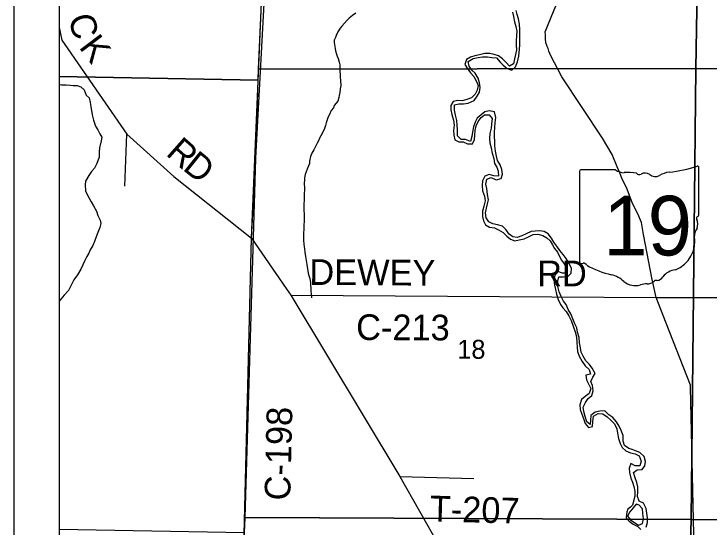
# Model space of a CAD drawing. Extents: x 0 to 34, y 0 to 22.
# Drawn here: x 2 to 3.538, y 17.445 to 18.58 of the extents above; entities that cross this region are included whole.
import ezdxf

# ---------------------------------------------------------------- set-up
doc = ezdxf.new("R2010")
doc.units = 0
for name, color, linetype in [('Default', 7, 'Continuous'), ('GM_X_County_Road', 7, 'Continuous'), ('GM_X_County_Road_Text', 7, 'Continuous'), ('GM_X_Minor_River', 7, 'Continuous'), ('GM_X_Section', 7, 'Continuous'), ('GM_X_Section_Text', 7, 'Continuous'), ('GM_X_State_Location', 7, 'Continuous'), ('GM_X_State_Route', 7, 'Continuous'), ('GM_X_State_Shield', 7, 'Continuous'), ('GM_X_Township', 7, 'Continuous'), ('GM_X_Township_Road', 7, 'Continuous'), ('GM_X_Township_Road_Text', 7, 'Continuous'), ('SH_Cut_Line', 7, 'Continuous'), ('SH_Data', 7, 'Continuous')]:
    doc.layers.add(name, color=color, linetype=linetype)

msp = doc.modelspace()

# ---------------------------------------------------------------- linework, layer by layer
at = {"layer": 'Default'}
for points in [[(2.1, 19.4698), (2.1, 18.4416), (2.54, 18.4332), (2.5413, 18.4578), (2.5849, 19.435)], [(2.1, 18.4416), (2.1, 17.4406), (2.5103, 17.4328), (2.5117, 17.4662), (2.54, 18.4332)]]:
    msp.add_lwpolyline(points, close=True, dxfattribs=at)
at = {"layer": 'GM_X_County_Road'}
for p, q in [((2.5258, 18.084), (2.5713, 18.9402)), ((2.5095, 17.4283), (2.5258, 18.084)), ((2.6125, 17.9578), (3.4203, 17.953))]:
    msp.add_line(p, q, dxfattribs=at)
for points in [[(2.1, 18.5494), (2.1061, 18.5215), (2.2501, 18.3137), (2.3537, 18.2205), (2.5258, 18.084)], [(2.5258, 18.084), (2.6022, 17.9726), (2.6125, 17.9578)], [(2.6125, 17.9578), (2.8536, 17.5572), (2.9844, 17.3269), (3.0036, 17.2741), (3.0215, 17.2032), (3.0902, 16.9681)], [(3.4203, 17.953), (3.775, 17.9527), (4.5096, 17.9519)]]:
    msp.add_lwpolyline(points, dxfattribs=at)
at = {"layer": 'GM_X_Minor_River'}
for points in [[(2.7565, 18.5813), (2.7488, 18.5761), (2.7415, 18.5701), (2.7369, 18.5656), (2.7254, 18.5528), (2.7219, 18.5479), (2.7162, 18.54), (2.7127, 18.5321), (2.7111, 18.5275), (2.7087, 18.5219), (2.7087, 18.5165), (2.7097, 18.5074), (2.7104, 18.5029), (2.7115, 18.4983), (2.7133, 18.4911), (2.7152, 18.4861), (2.717, 18.4808), (2.7196, 18.4728), (2.7206, 18.4675), (2.7209, 18.4595), (2.7208, 18.4526), (2.7215, 18.4458), (2.7218, 18.4401), (2.7225, 18.4325), (2.7231, 18.4215), (2.7219, 18.4143), (2.7211, 18.406), (2.7191, 18.3995), (2.7187, 18.395), (2.7163, 18.387), (2.7086, 18.3769), (2.7067, 18.3723), (2.702, 18.3659), (2.6978, 18.3576), (2.6954, 18.352), (2.6931, 18.3452), (2.6907, 18.3391), (2.6891, 18.333), (2.6868, 18.3262), (2.6833, 18.3183)], [(3.0478, 18.1805), (3.0462, 18.1938), (3.0438, 18.2033), (3.0464, 18.2147), (3.056, 18.2178), (3.0665, 18.2126), (3.0775, 18.2157), (3.0805, 18.2251), (3.0792, 18.2358), (3.0757, 18.2458), (3.0695, 18.2554), (3.0675, 18.2653), (3.0655, 18.276), (3.0639, 18.2878), (3.0634, 18.2973), (3.063, 18.3087), (3.0629, 18.3182), (3.0635, 18.3289), (3.0642, 18.3387), (3.0657, 18.3508), (3.063, 18.3634), (3.0513, 18.3656), (3.0413, 18.3629), (3.0332, 18.3566), (3.025, 18.3493), (3.0206, 18.3407), (3.0166, 18.3298), (3.014, 18.3184), (3.0129, 18.3086), (3.0096, 18.2977), (2.9991, 18.3021), (2.9893, 18.302), (2.9811, 18.3102), (2.9811, 18.3239), (2.9802, 18.3334), (2.9798, 18.3444), (2.9771, 18.3555), (2.9747, 18.3666), (2.9743, 18.3784), (2.9842, 18.3808), (2.9944, 18.3809), (3.0051, 18.3821), (3.0181, 18.3882), (3.0248, 18.3979), (3.03, 18.4068), (3.0314, 18.4171), (3.0302, 18.4273), (3.0267, 18.4373), (3.0205, 18.4485), (3.0127, 18.4552), (3.0073, 18.464), (3.0046, 18.4747), (3.0157, 18.4809), (3.0268, 18.4836), (3.0363, 18.4845), (3.0473, 18.485), (3.0571, 18.4832), (3.0677, 18.4829), (3.0758, 18.4732), (3.0824, 18.4662), (3.091, 18.4587), (3.1015, 18.455), (3.1093, 18.4624), (3.1141, 18.474), (3.1167, 18.4865), (3.1183, 18.5016), (3.1193, 18.5111), (3.1189, 18.5229), (3.1188, 18.5339), (3.1187, 18.5445), (3.1186, 18.5567), (3.1159, 18.5689), (3.1135, 18.5784), (3.1111, 18.5876)], [(3.1027, 18.5833), (3.1054, 18.5737), (3.1074, 18.5623), (3.1105, 18.5519), (3.1125, 18.5416), (3.1115, 18.5318), (3.1112, 18.5204), (3.1109, 18.5102), (3.1114, 18.5003), (3.1092, 18.4901), (3.1071, 18.4807), (3.1049, 18.4693), (3.096, 18.4639), (3.0887, 18.4721), (3.0809, 18.4806), (3.072, 18.4873), (3.0626, 18.4902), (3.0528, 18.492), (3.0418, 18.4919), (3.03, 18.4892), (3.0193, 18.4869), (3.0101, 18.4841)], [(3.0101, 18.4841), (3.0009, 18.479), (2.9972, 18.4681), (3.0022, 18.4596), (3.0096, 18.4496), (3.0173, 18.441), (3.0235, 18.4306), (3.0266, 18.4214), (3.0244, 18.4112), (3.02, 18.4026), (3.0119, 18.3944), (3.0015, 18.3902), (2.9916, 18.3874), (2.9817, 18.3884), (2.9718, 18.3864), (2.9666, 18.3771), (2.9668, 18.3676), (2.9688, 18.3573), (2.9726, 18.3446), (2.9738, 18.3336), (2.9727, 18.3219), (2.9728, 18.312), (2.9756, 18.3013), (2.9842, 18.2969), (2.994, 18.2966), (3.003, 18.2922), (3.014, 18.2926), (3.0188, 18.3024), (3.0195, 18.3118), (3.0201, 18.3221), (3.0223, 18.3323), (3.0271, 18.3416), (3.0334, 18.3509), (3.0412, 18.3568), (3.0514, 18.3565), (3.0576, 18.3488), (3.0565, 18.3363), (3.0555, 18.3268), (3.0529, 18.3151), (3.0523, 18.3045), (3.0528, 18.2946), (3.0555, 18.2835), (3.0578, 18.2717), (3.0613, 18.2602), (3.0633, 18.2491), (3.0684, 18.241), (3.0712, 18.2318), (3.0716, 18.2208), (3.0614, 18.2215), (3.0509, 18.2248), (3.042, 18.2209), (3.0365, 18.2108), (3.0358, 18.2002), (3.0366, 18.1887), (3.0408, 18.1769), (3.0425, 18.1662), (3.0395, 18.1549), (3.0365, 18.1436), (3.0362, 18.1318), (3.0386, 18.1219), (3.0433, 18.1134), (3.0519, 18.1082), (3.0628, 18.1068), (3.0722, 18.102), (3.0819, 18.0968), (3.09, 18.0886), (3.0982, 18.0819), (3.1079, 18.0778), (3.1179, 18.0802), (3.1285, 18.0822), (3.1385, 18.0868), (3.1485, 18.0919), (3.1588, 18.0931), (3.1697, 18.0898), (3.179, 18.0846), (3.1861, 18.0779), (3.1915, 18.0694), (3.1958, 18.061), (3.2021, 18.0532), (3.2067, 18.0436), (3.2114, 18.0351), (3.2173, 18.0274), (3.2227, 18.0177), (3.2239, 18.0067), (3.2133, 18.0062), (3.2032, 18.0099), (3.1961, 18.0021), (3.194, 17.9919), (3.1955, 17.9797), (3.1983, 17.9705), (3.2003, 17.9599), (3.2038, 17.9484), (3.2092, 17.9376), (3.2143, 17.9295), (3.2213, 17.9221), (3.2278, 17.9124), (3.2329, 17.902), (3.2381, 17.8874), (3.2413, 17.8767), (3.2444, 17.8656), (3.2452, 17.8531)], [(2.1, 18.4239), (2.1056, 18.4232), (2.1159, 18.4227), (2.1242, 18.4222), (2.1314, 18.4218), (2.1397, 18.4213), (2.1484, 18.4186), (2.1556, 18.412), (2.1596, 18.4002), (2.1667, 18.3944), (2.1689, 18.3842), (2.1703, 18.3751), (2.1728, 18.3564), (2.1757, 18.345), (2.1808, 18.3313), (2.1853, 18.3233), (2.1901, 18.3149), (2.1942, 18.3072), (2.193, 18.2989), (2.1894, 18.2838), (2.1889, 18.2743), (2.1884, 18.2629), (2.1837, 18.2489), (2.1779, 18.2387), (2.1717, 18.2316), (2.1655, 18.2221), (2.1586, 18.2101), (2.1573, 18.2021), (2.1587, 18.1884), (2.1631, 18.1793), (2.1709, 18.1644), (2.1761, 18.1552), (2.1825, 18.1438), (2.1858, 18.1342), (2.1906, 18.1239), (2.192, 18.1167), (2.19, 18.1073), (2.1857, 18.0963), (2.1822, 18.0868), (2.1779, 18.0766), (2.1748, 18.0679), (2.169, 18.0581), (2.1658, 18.0506), (2.1616, 18.043), (2.1569, 18.0347), (2.1484, 18.0155), (2.1403, 18.003), (2.1326, 17.9917), (2.1252, 17.977), (2.1209, 17.9683), (2.1109, 17.9578), (2.104, 17.9488), (2.1, 17.9444)], [(2.6833, 18.3183), (2.679, 18.3104), (2.6763, 18.3051), (2.6736, 18.2994), (2.6709, 18.2938), (2.6658, 18.284), (2.6631, 18.2791), (2.6588, 18.2715), (2.6557, 18.2647), (2.6541, 18.2545), (2.6537, 18.2492), (2.6517, 18.2439), (2.649, 18.2367), (2.6443, 18.225), (2.6431, 18.2174), (2.6426, 18.2128), (2.6421, 18.2049), (2.6424, 18.1946), (2.6424, 18.1901), (2.6419, 18.1825), (2.6415, 18.1442), (2.6418, 18.1385), (2.6421, 18.1316), (2.642, 18.1218), (2.6415, 18.1123), (2.6413, 18.1017), (2.6409, 18.0971), (2.6404, 18.0884), (2.6403, 18.0793), (2.641, 18.0705), (2.6417, 18.0648), (2.6424, 18.0603), (2.6434, 18.0527), (2.6449, 18.0435), (2.6474, 18.0302), (2.6481, 18.0257), (2.6491, 18.0162), (2.6498, 18.0116), (2.6509, 18.0067), (2.652, 18.0013), (2.6545, 17.9949), (2.6559, 17.9853), (2.6563, 17.9808), (2.6569, 17.9728), (2.6569, 17.9683), (2.6576, 17.9595), (2.6586, 17.9519)], [(3.1134, 18.0853), (3.1036, 18.0867), (3.0958, 18.093), (3.0878, 18.1034), (3.0808, 18.1105), (3.0695, 18.1134), (3.0597, 18.1156), (3.0507, 18.12), (3.0449, 18.1289), (3.0432, 18.1396), (3.0454, 18.1505), (3.0472, 18.16), (3.0501, 18.169), (3.0478, 18.1805)], [(3.3987, 17.4449), (3.4016, 17.4554), (3.4012, 17.4657), (3.4003, 17.4756), (3.3987, 17.4863), (3.3926, 17.4982), (3.3832, 17.5023), (3.3793, 17.513), (3.3803, 17.5236), (3.3799, 17.5342), (3.3779, 17.5438), (3.3743, 17.5541), (3.3705, 17.5656), (3.3786, 17.5715), (3.3893, 17.5727), (3.3955, 17.5805), (3.3969, 17.5904), (3.3938, 17.6011), (3.3846, 17.6101), (3.3751, 17.6137), (3.3677, 17.6164), (3.3602, 17.6191), (3.3509, 17.6254), (3.3477, 17.635), (3.3477, 17.6475), (3.3431, 17.659), (3.3384, 17.6683), (3.3326, 17.6776), (3.3245, 17.6876), (3.3156, 17.6936), (3.3071, 17.7018), (3.2957, 17.7013), (3.2854, 17.6993), (3.2764, 17.6916), (3.275, 17.6814), (3.2744, 17.6716), (3.267, 17.6778), (3.2635, 17.6893), (3.2604, 17.7004), (3.2595, 17.7099), (3.264, 17.7208), (3.2699, 17.7294), (3.278, 17.7364), (3.281, 17.7466), (3.2798, 17.758), (3.2758, 17.7672), (3.2803, 17.7769), (3.2858, 17.7848), (3.2793, 17.7963), (3.2734, 17.8045), (3.2653, 17.813), (3.2588, 17.8227), (3.2545, 17.8316), (3.2532, 17.8411), (3.2508, 17.8522), (3.25, 17.864), (3.2469, 17.8762), (3.2449, 17.8857), (3.241, 17.8946), (3.2364, 17.9053), (3.2321, 17.9165), (3.2263, 17.9265), (3.2213, 17.9369), (3.2158, 17.9446), (3.2104, 17.955), (3.2061, 17.9654), (3.203, 17.9773), (3.203, 17.9886), (3.2055, 17.9981), (3.2154, 17.9986), (3.2249, 17.9991), (3.2323, 18.0068), (3.2333, 18.0167), (3.2279, 18.0282), (3.2214, 18.0386), (3.2148, 18.0479), (3.2078, 18.0565), (3.2009, 18.0662), (3.1943, 18.0751), (3.1889, 18.0839), (3.1815, 18.0933), (3.1726, 18.0988), (3.1628, 18.0999), (3.1533, 18.0994), (3.1438, 18.0989), (3.133, 18.0935), (3.1234, 18.0892), (3.1134, 18.0853)], [(3.2452, 17.8531), (3.246, 17.8428), (3.2469, 17.8333), (3.2501, 17.823), (3.2566, 17.811), (3.2635, 17.8013), (3.2724, 17.7935), (3.2751, 17.7832), (3.2648, 17.7808), (3.2668, 17.7709), (3.2711, 17.7616), (3.2762, 17.7516), (3.2725, 17.7403), (3.2636, 17.7337), (3.2558, 17.7271), (3.2521, 17.7155), (3.2525, 17.7048), (3.2564, 17.6944), (3.26, 17.6849), (3.2635, 17.6738), (3.2708, 17.6652), (3.28, 17.6676), (3.2806, 17.6786), (3.2821, 17.6903), (3.2921, 17.6961), (3.3023, 17.6955), (3.3124, 17.6887), (3.3205, 17.6817), (3.3283, 17.6731), (3.3333, 17.662), (3.3353, 17.6524), (3.3376, 17.641), (3.3408, 17.6299), (3.3451, 17.621), (3.3536, 17.6136), (3.3641, 17.6091), (3.3739, 17.6073), (3.3829, 17.6025), (3.3875, 17.591), (3.3845, 17.5804), (3.3739, 17.5807), (3.3646, 17.5855), (3.3609, 17.575), (3.3614, 17.5655), (3.3645, 17.5529), (3.3684, 17.5441), (3.3715, 17.5345), (3.3735, 17.5246), (3.3736, 17.5135), (3.3682, 17.4936), (3.3639, 17.4895), (3.3577, 17.4847), (3.356, 17.4791), (3.3541, 17.4659), (3.3611, 17.4581), (3.3697, 17.4518), (3.3798, 17.4465), (3.3868, 17.4399)], [(3.3762, 17.4956), (3.3695, 17.4878), (3.3621, 17.4789), (3.3573, 17.4696), (3.3639, 17.4614), (3.3732, 17.4543), (3.3814, 17.4495), (3.3906, 17.4531), (3.3928, 17.4637)], [(3.3928, 17.4637), (3.3912, 17.4751), (3.3903, 17.4854), (3.3833, 17.4932), (3.3762, 17.4956)]]:
    msp.add_lwpolyline(points, dxfattribs=at)
at = {"layer": 'GM_X_Section'}
for points in [[(3.5253, 19.4614), (3.5082, 18.4594), (2.5413, 18.4578), (2.5849, 19.435), (2.5858, 19.465)], [(4.5252, 19.4639), (4.517, 18.4555), (3.5082, 18.4594), (3.5253, 19.4614)], [(3.5082, 18.4594), (3.4982, 17.462), (2.5117, 17.4662), (2.54, 18.4332), (2.5413, 18.4578)], [(4.517, 18.4555), (4.4991, 17.4554), (3.4982, 17.462), (3.5082, 18.4594)], [(3.4982, 17.462), (3.4692, 16.4646), (2.4877, 16.4726), (2.5103, 17.4328), (2.5117, 17.4662)], [(4.4991, 17.4554), (4.4826, 16.453), (3.4692, 16.4646), (3.4982, 17.462)]]:
    msp.add_lwpolyline(points, close=True, dxfattribs=at)
at = {"layer": 'GM_X_State_Route'}
msp.add_lwpolyline([(3.5068, 17.2998), (3.4971, 17.7208), (3.4968, 17.7546), (3.4965, 17.7592), (3.4424, 17.8956), (3.4203, 17.953), (3.4116, 17.9928), (3.3929, 18.0918), (3.388, 18.1189), (3.3803, 18.1376), (3.3689, 18.159), (3.3659, 18.1663), (3.3612, 18.1808), (3.355, 18.1957), (3.3454, 18.2144), (3.3399, 18.2282), (3.3341, 18.2415), (3.3231, 18.2687), (3.302, 18.305), (3.2122, 18.4404), (3.1956, 18.4717), (3.1879, 18.487), (3.1835, 18.4977), (3.1816, 18.5031), (3.1798, 18.5077), (3.1773, 18.5142), (3.1769, 18.5161), (3.1755, 18.5256), (3.1756, 18.529), (3.1757, 18.5343), (3.1754, 18.5404), (3.2116, 18.6305)], dxfattribs=at)
at = {"layer": 'GM_X_State_Shield'}
for p, q in [((3.5149, 18.1354), (3.5149, 18.2401)), ((3.2512, 18.2317), (3.2512, 18.0315)), ((3.331, 18.2351), (3.2538, 18.2351)), ((3.5149, 18.1354), (3.5149, 18.1354))]:
    msp.add_line(p, q, dxfattribs=at)
for centre, radius, start, end in [((3.421, 18.5079), 0.2796, 275.8445, 288.9065), ((3.512, 18.2405), 0.00294, 351.8621, 97.738), ((3.2542, 18.2321), 0.00305, 98.1301, 188.1301), ((3.3494, 18.2583), 0.0296, 231.6195, 271.1119), ((3.3592, 18.1228), 0.1064, 80.4867, 94.9883), ((3.3834, 18.2331), 0.00855, 219.7921, 297.1024), ((3.3959, 18.21), 0.0178, 54.4667, 119.1411), ((3.4189, 18.2417), 0.0214, 233.8562, 294.8282), ((3.4566, 18.174), 0.0563, 97.3462, 120.7689), ((3.5142, 18.1277), 0.00454, 107.944, 210.337), ((3.5118, 18.135), 0.00314, 289.6038, 7.7341), ((3.4853, 18.1145), 0.0273, 340.033, 23.6496), ((3.5254, 18.0916), 0.0198, 136.8065, 186.9296), ((3.4366, 18.0783), 0.0699, 292.3089, 8.9858), ((3.2543, 18.0311), 0.00308, 171.9584, 258.3066), ((3.2547, 18.0516), 0.0235, 267.339, 280.6039), ((3.2595, 18.02), 0.00848, 29.7484, 93.2717), ((3.3666, 18.1998), 0.2019, 240.4129, 257.1985), ((3.4661, 17.9754), 0.0383, 94.4031, 142.5768), ((3.3064, 17.9416), 0.0632, 47.1842, 75.836), ((3.4176, 18.0121), 0.0226, 282.8732, 323.2771), ((3.3747, 18.019), 0.0401, 230.7004, 286.2918), ((3.3979, 17.9498), 0.0329, 85.6951, 111.2099), ((3.4008, 18.004), 0.0214, 268.777, 315.5493), ((3.4201, 17.9846), 0.00601, 65.7517, 132.6484)]:
    msp.add_arc(centre, radius, start, end, dxfattribs=at)
at = {"layer": 'GM_X_Township'}
msp.add_lwpolyline([(2.5093, 17.4289), (2.5256, 18.0846), (2.5616, 18.9348), (2.5619, 18.941), (2.5631, 18.9701), (2.6034, 19.9491), (2.6035, 19.9525), (2.6217, 20.3636), (2.6265, 20.3636), (2.7999, 20.363), (2.8069, 20.3629), (2.814, 20.3628), (2.8217, 20.3627), (3.5356, 20.3768), (3.5731, 20.3768), (3.6279, 20.3774), (4.0307, 20.3846), (4.54, 20.3955), (4.5784, 20.3968), (5.284, 20.4086)], dxfattribs=at)
at = {"layer": 'GM_X_Township_Road'}
for p, q in [((2.2452, 18.1987), (2.2501, 18.3137)), ((2.8536, 17.5572), (3.0176, 17.5527))]:
    msp.add_line(p, q, dxfattribs=at)
msp.add_lwpolyline([(2.4116, 15.0173), (2.4334, 15.5145), (2.4339, 15.5244), (2.4986, 16.925), (2.5003, 16.9626), (2.5093, 17.4289), (2.5256, 18.0846), (2.5616, 18.9348), (2.5619, 18.941), (2.5631, 18.9701), (2.6034, 19.9491), (2.6035, 19.9525), (2.6217, 20.3636), (2.1208, 20.3735), (2.1108, 20.3737), (2.1, 20.3739), (2.1, 14.5206)], dxfattribs=at)
at = {"layer": 'SH_Cut_Line'}
msp.add_lwpolyline([(8.9, 20.9), (2.1, 20.9), (2.1, 14.5206)], dxfattribs=at)
at = {"layer": 'SH_Data'}
for p, q in [((2, 21), (2, 14)), ((2.1, 20.9), (2.1, 14.1))]:
    msp.add_line(p, q, dxfattribs=at)

# ---------------------------------------------------------------- texts
at = {"layer": 'GM_X_County_Road_Text'}
for s, height, rotation, p in [('C', 0.0568, 285.5303, (2.1197, 18.5718)), ('K', 0.0568, 306.946, (2.1424, 18.5062)), ('R', 0.0568, 318.5831, (2.3342, 18.269)), ('D', 0.0568, 321.2116, (2.3713, 18.2363)), ('DEWEY', 0.05682, 359.6191, (2.6534, 17.9807)), ('RD', 0.05682, 0, (3.1574, 17.9774)), ('C-213', 0.05682, 359.7247, (2.7569, 17.8588)), ('C-198', 0.05682, 88.6237, (2.6111, 17.5035))]:
    msp.add_text(s, height=height, rotation=rotation, dxfattribs=at).set_placement(p)
at = {"layer": 'GM_X_Section_Text'}
msp.add_text('18', height=0.04186, rotation=0, dxfattribs=at).set_placement((2.9807, 17.8172))
at = {"layer": 'GM_X_State_Location'}
for s in ['s', 'r']:
    msp.add_text(s, height=0.000189, dxfattribs=at).set_placement((3.3801, 18.1183))
msp.add_text('19', height=0.000189, rotation=0, dxfattribs=at).set_placement((3.3324, 18.1045))
at = {"layer": 'GM_X_State_Shield'}
msp.add_text('19', height=0.13184, dxfattribs=at).set_placement((3.3038, 18.0457))
at = {"layer": 'GM_X_Township_Road_Text'}
msp.add_text('T-207', height=0.05682, rotation=358.4309, dxfattribs=at).set_placement((2.9193, 17.458))

doc.saveas('drawing.dxf')
